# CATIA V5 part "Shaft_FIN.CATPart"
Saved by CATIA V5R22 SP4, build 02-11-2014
Part number: Shaft
Bounding box of the stored display mesh (mm): x -20 to 20, y -95 to 95, z -14.99 to 32
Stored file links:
  C:\DATA\Car_ASSY\教育モデル\9_EXE\Shaft_FIN.CATPart
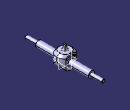
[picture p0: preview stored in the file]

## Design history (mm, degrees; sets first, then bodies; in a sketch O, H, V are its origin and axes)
Set1
  Plane1: type Offset, RefPlane end face of Pad1, Offset 6, reversed
  Plane2: type Offset, RefPlane end face of Pad1, Offset 12, reversed
  Extremum1: Reference Sketch4, Direction (1, 2, 3)
  Extremum2: Reference Sketch5, Direction (1, 2, 3)
  Extremum3: Reference Sketch6, Direction (1, 2, 3)
Body1 (main body)
  Body2
    Sketch1 on xy-plane, origin (0, 0, 0), H (1, 0, 0), V (0, 1, 0)
      circle A1 centre (0, 0) radius 20
      radius A1 = 20
    Pad1: profile Sketch1, direction (0, 0, 1), length 20, opposite side length 35
    Body3
      Sketch2 on zx-plane, origin (0, 0, 0), H (-1, 0, 0), V (0, 0, 1)
        line L1 (-20, 31.1043) -> (-20, 5)
        arc A1 centre (0, 5) radius 20 from (-20, 5) to (20, 5) ccw
        point P3 (0, 5)
        line L2 (20, 5) -> (20, 31.1043)
        line L3 (20, 31.1043) -> (-20, 31.1043)
        radius A1 = 20
        distance P3 H = 5
        vertical: L1 V
        tangency: A1 L1, L2 A1
        horizontal: L3 H
        symmetry: L1 L2 V
      Pad2: profile Sketch2, direction (0, 1, 0), length 30, mirrored extent
    Intersect1: tool Body3
    Chamfer1: length 6, angle 45, on edge [face of Pad1 from Sketch1.A1 | end face of Pad1]
    Loft1: solid, Sections (Sketch4; Sketch5; Sketch6)
    Sketch3 on xy-plane, origin (0, 0, 0), H (1, 0, 0), V (0, 1, 0)
      line L1 (-25, 15) -> (25, 15)
      line L2 (25, 15) -> (25, 25)
      line L3 (25, 25) -> (-25, 25)
      line L4 (-25, 25) -> (-25, 15)
      line L5 (-25, -15) -> (25, -15)
      line L6 (25, -15) -> (25, -25)
      line L7 (25, -25) -> (-25, -25)
      line L8 (-25, -25) -> (-25, -15)
      distance L1 H = 15
      horizontal: L1 H, L3 H, L5 H, L7 H
      vertical: L2 V, L4 V, L6 V, L8 V
      symmetry: L1 L5 H, L6 L8 V
    Pocket1: profile Sketch3, direction (0, 0, -1), length 30, mirrored extent
    Sketch4 on end face of Pad1, origin (0, 0, 20), H (1, 0, 0), V (0, 1, 0)
      line L1 (-5, 5) -> (5, 5)
      line L2 (5, 5) -> (5, -5)
      line L3 (5, -5) -> (-5, -5)
      line L4 (-5, -5) -> (-5, 5)
      length L2 = 10
      length L1 = 10
      horizontal: L1 H, L3 H
      vertical: L2 V, L4 V
      symmetry: L2 L4 V, L1 L3 H
    Sketch5 on Plane1, origin (0, 0, 26), H (1, 0, 0), V (0, 1, 0)
      construction line L1 through (0, 0) direction (1, 0)
      line L2 (-2.5, 2.5) -> (2.5, 2.5)
      line L3 (2.5, -2.5) -> (-2.5, -2.5)
      construction line L4 through (0, 0) direction (0, 1)
      line L5 (2.5, 2.5) -> (2.5, -2.5)
      line L6 (-2.5, -2.5) -> (-2.5, 2.5)
      point P1 (0, 0)
      length L5 = 5
      length L2 = 5
      horizontal: L2 L1, L3 L1
      vertical: L5 L4, L6 L4
      symmetry: L5 L6 L4, L2 L3 L1
      coincidence: L1 H, L4 V
    Sketch6 on Plane2, origin (0, 0, 32), H (1, 0, 0), V (0, 1, 0)
      construction line L1 through (0, 0) direction (1, 0)
      line L2 (-1.5, 2.5) -> (1.5, 2.5)
      line L3 (1.5, -2.5) -> (-1.5, -2.5)
      construction line L4 through (0, 0.2002) direction (0, 1)
      line L5 (1.5, 2.5) -> (1.5, -2.5)
      line L6 (-1.5, -2.5) -> (-1.5, 2.5)
      point P1 (0, 0)
      length L5 = 5
      length L2 = 3
      horizontal: L2 L1, L3 L1
      vertical: L5 L4, L6 L4
      symmetry: L5 L6 L4, L2 L3 L1
      coincidence: L1 H, L4 V
    Body4
      Sketch7 on zx-plane, origin (0, 0, 0), H (-1, 0, 0), V (0, 0, 1)
        circle A1 centre (0, 0) radius 7.5
        radius A1 = 7.5
      Pad3: profile Sketch7, direction (0, 1, 0), up to face of Pocket1 from Sketch3.L1, offset 50, opposite side up to face of Pocket1 from Sketch3.L5, offset 50
      Sketch8 on zx-plane, origin (0, 0, 0), H (-1, 0, 0), V (0, 0, 1)
        circle A1 centre (0, 0) radius 4
        radius A1 = 4
      Pad4: profile Sketch8, direction (0, 1, 0), up to end face of Pad3, offset 30, opposite side up to start face of Pad3, offset 30
      Chamfer2: length 1, angle 45, on edge [end face of Pad4 | face of Pad4 from Sketch8.A1]; edge [start face of Pad4 | face of Pad4 from Sketch8.A1]
    Add1: tool Body4
    Body5
      Sketch9 on yz-plane, origin (0, 0, 0), H (0, 1, 0), V (0, 0, 1)
        circle A1 centre (16, 14) radius 2
        point P1 (16, 14)
        reference intersected line E1 (-20, 20) -> (20, 20) from end face of Pad1
        reference intersected line E2 (15, -30) -> (15, 30) from face of Pocket1 from Sketch3.L1
        radius A1 = 2
        distance E1 P1 = 6
        distance E2 P1 = 1
      Sketch10 on face of Pocket1 from Sketch3.L1, origin (0, 15, 0), H (-1, 0, 0), V (0, 0, 1)
        offset curve E1 from edge [face of Pocket1 from Sketch3.L1 | face of Chamfer1]
      Rib1: profile Sketch9, centre curve Sketch10
      Sketch11 on yz-plane, origin (0, 0, 0), H (0, 1, 0), V (0, 0, 1)
        circle A1 centre (-16, 14) radius 2
        point P1 (-16, 14)
        reference intersected line E1 (-20, 20) -> (20, 20) from end face of Pad1
        reference intersected line E2 (-15, 30) -> (-15, -30) from face of Pocket1 from Sketch3.L5
        radius A1 = 2
        distance E1 P1 = 6
        distance E2 P1 = 1
      Sketch12 on face of Pocket1 from Sketch3.L5, origin (0, -15, 0), H (1, 0, 0), V (0, 0, 1)
        offset curve E1 from edge [face of Pocket1 from Sketch3.L5 | face of Chamfer1]
      Rib2: profile Sketch11, centre curve Sketch12
    Remove1: tool Body5
  Add2: tool Body2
